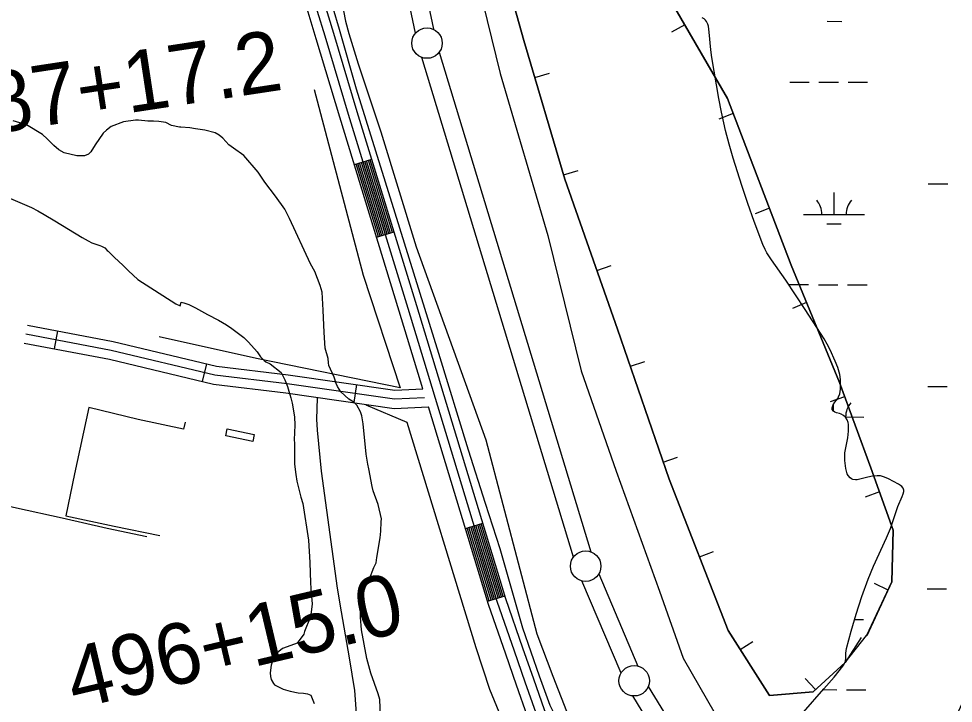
# Model space of a CAD drawing. Extents: x 3161615 to 3199515, y 867541 to 892976.
# Drawn here: x 3176709 to 3178243, y 879602 to 880727 of the extents above; entities that cross this region are included whole.
import ezdxf

# ---------------------------------------------------------------- set-up
doc = ezdxf.new("R2010")
doc.units = 0
for name, color, linetype in [('V-BLDG-OTLN', 7, 'Continuous'), ('V-BORW-LINE', 7, 'Continuous'), ('V-LEVE-TOET', 7, 'Continuous'), ('V-ROAD-CNTR', 7, 'Continuous'), ('V-SITE-VEGE', 7, 'Continuous'), ('V-SURV-IDEN', 7, 'Continuous'), ('V-SURV-LINE', 7, 'Continuous'), ('V-TOPO-SHOR', 7, 'Continuous'), ('V-UTIL-LINE', 7, 'Continuous'), ('V-WETL-SWMP', 7, 'Continuous')]:
    doc.layers.add(name, color=color, linetype=linetype)

msp = doc.modelspace()

# ---------------------------------------------------------------- linework, layer by layer
at = {"layer": 'V-BLDG-OTLN'}
msp.add_lwpolyline([(3177048.5, 880041.9), (3177050.9, 880053.1), (3177095.5, 880043.7), (3177093.1, 880032.4)], close=True, dxfattribs=at)
at = {"layer": 'V-BORW-LINE'}
for p, q in [((3177802.3, 880717.1), (3177780.7, 880704.6)), ((3177556.2, 880630.3), (3177580.2, 880637.3)), ((3177881.9, 880571.1), (3177858.6, 880562.2)), ((3177603.1, 880470.4), (3177627.1, 880477.5)), ((3177941.4, 880415.5), (3177918, 880406.6)), ((3177658.2, 880313.2), (3177681.7, 880321.5)), ((3178002.3, 880260.5), (3177979.2, 880251)), ((3177713.1, 880155.9), (3177736.7, 880164)), ((3178064.8, 880106), (3178041.3, 880097.4)), ((3177767.1, 879998.3), (3177790.7, 880006.4)), ((3178122.1, 879949.6), (3178098.6, 879941)), ((3177826.4, 879842.7), (3177849.7, 879851.7)), ((3178136.5, 879788.4), (3178113.8, 879798.9)), ((3177893.4, 879690.7), (3177914.4, 879704.1)), ((3178016.9, 879624.7), (3178000.1, 879643.1))]:
    msp.add_line(p, q, dxfattribs=at)
for points in [[(3177906.6, 882507), (3177867.3, 882300.3), (3177808.7, 882150.3), (3177775.1, 881987.1), (3177749.8, 881843.1), (3177713.2, 881626.3), (3177674.2, 881366.1), (3177662.8, 881291.6), (3177659.6, 881039.8), (3177733, 880836.9), (3177872.5, 880595.9), (3177977.1, 880322), (3178056.3, 880129.2), (3178107.7, 879988.9), (3178144.8, 879887), (3178142.7, 879801.7), (3178101.3, 879712.9)], [(3178092.2, 879710.3), (3178065.6, 879669.2), (3178013.2, 879621.3), (3177941.5, 879615.1), (3177873.5, 879721.9), (3177776.5, 879970.7), (3177692.1, 880217), (3177605.2, 880463.4), (3177538.3, 880691.4), (3177480.8, 880896.9), (3177471.8, 881055.7), (3177486.2, 881218), (3177566.2, 881651.6), (3177659.6, 882084.4), (3177695.5, 882282.8), (3177716.7, 882419.5), (3177742.6, 882484.1)], [(3177742.6, 882484.1), (3177716.7, 882419.5), (3177695.5, 882282.8), (3177659.6, 882084.4), (3177566.2, 881651.6), (3177486.2, 881218), (3177471.8, 881055.7), (3177480.8, 880896.9), (3177538.3, 880691.4), (3177605.2, 880463.4), (3177692.1, 880217), (3177776.5, 879970.7), (3177873.5, 879721.9), (3177941.5, 879615.1), (3178013.2, 879621.3), (3178065.6, 879669.2), (3178100.9, 879713.6)], [(3178100.7, 879713), (3178142.7, 879801.7), (3178144.8, 879887), (3178107.7, 879988.9), (3178056.3, 880129.2), (3177977.1, 880322), (3177872.5, 880595.9), (3177733, 880836.9), (3177659.6, 881039.8), (3177662.8, 881291.6), (3177674.2, 881366.1), (3177713.2, 881626.3), (3177749.8, 881843.1), (3177765.7, 881933.1)]]:
    msp.add_lwpolyline(points, dxfattribs=at)
at = {"layer": 'V-LEVE-TOET'}
for points in [[(3177190.1, 881032.5), (3177212.4, 880895.6), (3177219.4, 880848.2), (3177238.4, 880756.8), (3177245.2, 880722.9), (3177250.9, 880702.4), (3177266.2, 880652.8), (3177303.4, 880541.3), (3177361.3, 880352), (3177475.6, 880035.3), (3177559.5, 879716.2), (3177585.5, 879647.1), (3177608.2, 879589.3), (3177632.1, 879544), (3177652.9, 879510.5), (3177737.9, 879384.6), (3177804.7, 879295.2), (3177918.6, 879156.7), (3178101.7, 878928.5)], [(3177412.9, 881027.8), (3177449.1, 880843), (3177499.5, 880636.8), (3177577.4, 880371), (3177632.4, 880148.7), (3177689.7, 879983.7), (3177760.7, 879786.6), (3177799.6, 879676.6)], [(3177799.6, 879676.6), (3177852.3, 879585), (3177964.5, 879433.7), (3178065.3, 879314.6), (3178143.2, 879225.2), (3178214.2, 879147.3), (3178232.6, 879117.5), (3178237.1, 879094.6), (3178257.8, 878964), (3178260, 878945.7), (3178276.1, 878931.9), (3178427.3, 878842.5), (3178633.4, 878741.7), (3178715.9, 878700.5), (3178725, 878700.5), (3178768.6, 878698.2), (3179196.9, 878711.9), (3179522.2, 878730.3), (3179932.2, 878739.4), (3180383.5, 878760.1), (3180724.8, 878771.5)]]:
    msp.add_lwpolyline(points, dxfattribs=at)
at = {"layer": 'V-ROAD-CNTR'}
for p, q in [((3177259.8, 880487.4), (3177288.5, 880496.2)), ((3177296.4, 880367.9), (3177325.1, 880376.7)), ((3176772.3, 880214.2), (3176766.7, 880184.8)), ((3177017, 880160.2), (3177010.1, 880131)), ((3177263.2, 880126), (3177258.9, 880096.3)), ((3177442.2, 879889.6), (3177470.9, 879898.4)), ((3177478.6, 879770), (3177507.3, 879778.8))]:
    msp.add_line(p, q, dxfattribs=at)
for points in [[(3177372.4, 880118.9), (3177333.6, 880246.4), (3177235.9, 880565.3), (3177197.2, 880693.8), (3177172.3, 880776.4), (3177154, 880867.6), (3177149.1, 880924.8), (3177136.4, 880983.8), (3177130.2, 881055.1), (3177129, 881145.4), (3177132.9, 881223.7), (3177140, 881329.3), (3177184.4, 881632.9), (3177269.1, 882075.3), (3177338.3, 882444.5), (3177405.5, 882803.5), (3177445.5, 883028.2)], [(3177983.4, 878986.1), (3177974, 879017.1), (3177947.6, 879056.2), (3177906.3, 879105.1), (3177789.6, 879242.6), (3177686.3, 879377.3), (3177649.8, 879426.9), (3177610.6, 879487.5), (3177583.1, 879532.7), (3177558.2, 879586.1), (3177540.3, 879636.8), (3177522.5, 879688.1), (3177494.5, 879769.3), (3177348, 880250.8), (3177250.3, 880569.6), (3177211.6, 880698.1), (3177186.8, 880780.1)], [(3177997.7, 878990.5), (3177987.7, 879023.6), (3177959.5, 879065.3), (3177917.7, 879114.8), (3177801.3, 879252), (3177698.3, 879386.4), (3177662.1, 879435.4), (3177623.3, 879495.4), (3177596.3, 879539.8), (3177572.1, 879591.7), (3177554.5, 879641.8), (3177536.7, 879693.1), (3177508.7, 879774), (3177362.3, 880255.1), (3177264.6, 880574), (3177225.9, 880702.4), (3177201.4, 880783.7)], [(3177322.2, 880375.8), (3177285.6, 880495.3)], [(3177299.3, 880368.8), (3177262.7, 880488.3)], [(3177302.2, 880369.6), (3177265.5, 880489.1)], [(3177305, 880370.5), (3177268.4, 880490)], [(3177307.9, 880371.4), (3177271.3, 880490.9)], [(3177310.8, 880372.3), (3177274.1, 880491.8)], [(3177313.6, 880373.1), (3177277, 880492.7)], [(3177316.5, 880374), (3177279.9, 880493.5)], [(3177319.4, 880374.9), (3177282.8, 880494.4)], [(3176723.2, 880223.6), (3176863.8, 880196.8), (3177033.5, 880156.3), (3177151.2, 880142.1), (3177326.4, 880116.9), (3177372.4, 880118.9)], [(3177374.7, 880104), (3177325.7, 880101.8), (3177149.3, 880127.2), (3177030.8, 880141.5), (3176860.6, 880182.1), (3176720.4, 880208.9)], [(3176717.6, 880194.2), (3176857.5, 880167.5), (3177028.2, 880126.7), (3177147.3, 880112.3), (3177324.9, 880086.8), (3177381.4, 880089.3)], [(3177955.1, 878644.3), (3177980.3, 878696.2), (3177990.9, 878727.9), (3178000, 878775.1), (3178003.8, 878817), (3177999.2, 878855.2), (3177993.5, 878899.8), (3177979.8, 878946.2), (3177969, 878981.8), (3177960.3, 879010.6), (3177935.6, 879047.2), (3177894.8, 879095.4), (3177777.9, 879233.1), (3177674.4, 879368.3), (3177637.4, 879418.3), (3177597.9, 879479.5), (3177569.8, 879525.6), (3177544.3, 879580.4), (3177526.2, 879631.9), (3177508.4, 879683.2), (3177480.2, 879764.7), (3177381.4, 880089.3)], [(3177504.4, 879777.9), (3177468, 879897.5)], [(3177481.4, 879770.9), (3177445.1, 879890.5)], [(3177484.3, 879771.8), (3177447.9, 879891.4)], [(3177487.2, 879772.7), (3177450.8, 879892.2)], [(3177490, 879773.5), (3177453.7, 879893.1)], [(3177492.9, 879774.4), (3177456.5, 879894)], [(3177495.8, 879775.3), (3177459.4, 879894.9)], [(3177498.7, 879776.1), (3177462.3, 879895.7)], [(3177501.5, 879777), (3177465.1, 879896.6)]]:
    msp.add_lwpolyline(points, dxfattribs=at)
at = {"layer": 'V-SITE-VEGE'}
for p, q in [((3176721.3, 880552.5), (3176699.5, 880559.3)), ((3176880.4, 880557.4), (3176860.2, 880550.1)), ((3176900.6, 880560.4), (3176880.4, 880557.4)), ((3176905.3, 880560.4), (3176900.6, 880560.4)), ((3176920.8, 880558.9), (3176905.3, 880560.4)), ((3176929.8, 880558.9), (3176920.8, 880558.9)), ((3176938.9, 880558.2), (3176929.8, 880558.9)), ((3176950, 880556.4), (3176938.9, 880558.2)), ((3176747.5, 880536.5), (3176721.3, 880552.5)), ((3176852.8, 880544.1), (3176847, 880538.8)), ((3176860.2, 880550.1), (3176852.8, 880544.1)), ((3176959.7, 880551.7), (3176950, 880556.4)), ((3176972.8, 880548.9), (3176959.7, 880551.7)), ((3176974.8, 880548.9), (3176972.8, 880548.9)), ((3176989.6, 880547.9), (3176974.8, 880548.9)), ((3176999, 880546.1), (3176989.6, 880547.9)), ((3177014.2, 880543.7), (3176999, 880546.1)), ((3177031.3, 880539.6), (3177014.2, 880543.7)), ((3176755.2, 880529.8), (3176747.5, 880536.5)), ((3176766.2, 880518.6), (3176755.2, 880529.8)), ((3176847, 880538.8), (3176834.1, 880519.7)), ((3177038, 880535.5), (3177031.3, 880539.6)), ((3177043.7, 880530.8), (3177038, 880535.5)), ((3177053.7, 880519.6), (3177043.7, 880530.8)), ((3176774.3, 880511.5), (3176766.2, 880518.6)), ((3176783, 880506.8), (3176774.3, 880511.5)), ((3176834.1, 880519.7), (3176827, 880508.3)), ((3177061.1, 880514.2), (3177053.7, 880519.6)), ((3177078.2, 880502.4), (3177061.1, 880514.2)), ((3176804.1, 880501.6), (3176783, 880506.8)), ((3176816.6, 880501.9), (3176804.1, 880501.6)), ((3176823, 880504.2), (3176816.6, 880501.9)), ((3176827, 880508.3), (3176823, 880504.2)), ((3177101.6, 880474.7), (3177078.2, 880502.4)), ((3177113, 880458.5), (3177101.6, 880474.7)), ((3177130.3, 880435.6), (3177113, 880458.5)), ((3176687.5, 880434.9), (3176729.8, 880416.9)), ((3177145.4, 880414), (3177130.3, 880435.6)), ((3176729.8, 880416.9), (3176739.8, 880411.5)), ((3176739.8, 880411.5), (3176750.2, 880405.4)), ((3176750.2, 880405.4), (3176768, 880394.9)), ((3177153.4, 880398.8), (3177145.4, 880414)), ((3176768, 880394.9), (3176812.6, 880367.8)), ((3177187.7, 880324), (3177153.4, 880398.8)), ((3176812.6, 880367.8), (3176822.7, 880362.3)), ((3176822.7, 880362.3), (3176828.4, 880359)), ((3176828.4, 880359), (3176833.4, 880356.9)), ((3176833.4, 880356.9), (3176841.8, 880354.2)), ((3176841.8, 880354.2), (3176844.5, 880353.2)), ((3176844.5, 880353.2), (3176849.8, 880350.5)), ((3176849.8, 880350.5), (3176853.9, 880346.4)), ((3176853.9, 880346.4), (3176855.5, 880345)), ((3176855.5, 880345), (3176865.9, 880334.6)), ((3176865.9, 880334.6), (3176879.3, 880322.1)), ((3176879.3, 880322.1), (3176888.7, 880312.9)), ((3176888.7, 880312.9), (3176904.4, 880298.4)), ((3177194.7, 880311.5), (3177187.7, 880324)), ((3177203.6, 880288.6), (3177194.7, 880311.5)), ((3176904.4, 880298.4), (3176966.4, 880258.8)), ((3177206.9, 880277.5), (3177203.6, 880288.6)), ((3177208.5, 880248.2), (3177206.9, 880277.5)), ((3176966.4, 880258.8), (3176973.8, 880255)), ((3176973.8, 880255), (3176975.5, 880261.4)), ((3176975.5, 880261.4), (3176979.9, 880260.4)), ((3176979.9, 880260.4), (3176987.9, 880257.7)), ((3176987.9, 880257.7), (3176999, 880252.2)), ((3176999, 880252.2), (3177018.8, 880241.1)), ((3177018.8, 880241.1), (3177036.6, 880231.6)), ((3177210, 880211.2), (3177208.5, 880248.2)), ((3177036.6, 880231.6), (3177050, 880224.1)), ((3177050, 880224.1), (3177058.4, 880218.3)), ((3177058.4, 880218.3), (3177078.5, 880203.1)), ((3177211.9, 880185.7), (3177210, 880211.2)), ((3177078.5, 880203.1), (3177086.2, 880195.7)), ((3177086.2, 880195.7), (3177099.9, 880179.5)), ((3177099.9, 880179.5), (3177105.9, 880171.4)), ((3177216.5, 880168.8), (3177211.9, 880185.7)), ((3177105.9, 880171.4), (3177111.6, 880165.3)), ((3177111.6, 880165.3), (3177114.6, 880163.3)), ((3177114.6, 880163.3), (3177121.3, 880160.2)), ((3177121.3, 880160.2), (3177139.7, 880146)), ((3177217.2, 880161.4), (3177216.5, 880168.8)), ((3177217.8, 880157.4), (3177217.2, 880161.4)), ((3177139.7, 880146), (3177145.7, 880133.5)), ((3177226.5, 880138.2), (3177217.8, 880157.4)), ((3177145.7, 880133.5), (3177150.1, 880122.7)), ((3177230.1, 880127.8), (3177226.5, 880138.2)), ((3177232.1, 880122.7), (3177230.1, 880127.8)), ((3177150.1, 880122.7), (3177152.4, 880115.3)), ((3177152.4, 880115.3), (3177155.7, 880104.2)), ((3177237.4, 880113.9), (3177232.1, 880122.7)), ((3177250.5, 880102.1), (3177237.4, 880113.9)), ((3177155.7, 880104.2), (3177157.7, 880095.5)), ((3177258.9, 880097), (3177250.5, 880102.1)), ((3177263.9, 880091.9), (3177258.9, 880097)), ((3177157.7, 880095.5), (3177161.6, 880072.9)), ((3177269.9, 880081.2), (3177263.9, 880091.9)), ((3177271.9, 880074.4), (3177269.9, 880081.2)), ((3177161.6, 880072.9), (3177162.2, 880059.5)), ((3177274.5, 880061.6), (3177271.9, 880074.4)), ((3177162.2, 880059.5), (3177161.1, 880034.9)), ((3177279.3, 880011.5), (3177274.5, 880061.6)), ((3177161.1, 880034.9), (3177161.4, 880029.5)), ((3177161.4, 880029.5), (3177161.6, 879995.2)), ((3177282, 879995.4), (3177279.3, 880011.5)), ((3177161.6, 879995.2), (3177163.8, 879978.1)), ((3177283.6, 879987.6), (3177282, 879995.4)), ((3177163.8, 879978.1), (3177165.1, 879967)), ((3177289.2, 879958.3), (3177283.6, 879987.6)), ((3177165.1, 879967), (3177171.7, 879941.1)), ((3177290.8, 879951.3), (3177289.2, 879958.3)), ((3177298.8, 879928.7), (3177290.8, 879951.3)), ((3177171.7, 879941.1), (3177175.1, 879930.6)), ((3177175.1, 879930.6), (3177184.2, 879870.4)), ((3177304.1, 879905.5), (3177298.8, 879928.7)), ((3177303, 879885.3), (3177304, 879900.4)), ((3177304, 879900.4), (3177304.1, 879905.5)), ((3177301.9, 879873.9), (3177303, 879885.3)), ((3177184.2, 879870.4), (3177186.4, 879833.4)), ((3177296.7, 879842), (3177301.9, 879873.9)), ((3177295.7, 879833.2), (3177296.7, 879842)), ((3177186.4, 879833.4), (3177187.6, 879800.4)), ((3177284.8, 879807), (3177291.6, 879825.2)), ((3177291.6, 879825.2), (3177295.7, 879833.2)), ((3177278.3, 879794.3), (3177284.8, 879807)), ((3177187.6, 879800.4), (3177188.2, 879791.4)), ((3177188.2, 879791.4), (3177188.2, 879789)), ((3177272.2, 879776.2), (3177278.3, 879794.3)), ((3177188.2, 879789), (3177190.4, 879765.8)), ((3177269.8, 879764.1), (3177272.2, 879776.2)), ((3177190.4, 879765.8), (3177189, 879752)), ((3177270, 879743.9), (3177269.8, 879764.1)), ((3177187.3, 879743.3), (3177177.8, 879720.1)), ((3177189, 879752), (3177187.3, 879743.3)), ((3177271.6, 879723), (3177270, 879743.9)), ((3177176.7, 879715.7), (3177165.6, 879701.3)), ((3177177.8, 879720.1), (3177176.7, 879715.7)), ((3177280.1, 879675.9), (3177271.6, 879723)), ((3177165.6, 879701.3), (3177149.4, 879695)), ((3177132.9, 879685), (3177128.8, 879680)), ((3177141.7, 879692.4), (3177132.9, 879685)), ((3177149.4, 879695), (3177141.7, 879692.4)), ((3177127.1, 879677.3), (3177123, 879665.2)), ((3177128.8, 879680), (3177127.1, 879677.3)), ((3177287.1, 879652), (3177280.1, 879675.9)), ((3177123, 879665.2), (3177121.6, 879652.5)), ((3177121.6, 879652.5), (3177121.9, 879646.4)), ((3177298.7, 879618), (3177287.1, 879652)), ((3177121.9, 879646.4), (3177123.3, 879641.3)), ((3177123.3, 879641.3), (3177126.9, 879634.6)), ((3177126.9, 879634.6), (3177128.9, 879632.9)), ((3177128.9, 879632.9), (3177142.7, 879625.5)), ((3177142.7, 879625.5), (3177154.4, 879622)), ((3177154.4, 879622), (3177167.5, 879619.6)), ((3177167.5, 879619.6), (3177176, 879618.9)), ((3177176, 879618.9), (3177182.7, 879617.9)), ((3177182.7, 879617.9), (3177188.4, 879615.5)), ((3177188.4, 879615.5), (3177194, 879601.7)), ((3177301.7, 879608.6), (3177298.7, 879618)), ((3177302.9, 879581), (3177301.7, 879608.6))]:
    msp.add_line(p, q, dxfattribs=at)
for points in [[(3178066.1, 880072.5), (3178063, 880075.3), (3178059.5, 880077.4), (3178056.4, 880078.6), (3178051.4, 880079.7), (3178048.9, 880080.6), (3178046.6, 880082.4), (3178044.6, 880085.1), (3178044.2, 880086.5), (3178044.3, 880087.9), (3178046.2, 880092.5), (3178048.8, 880097.1), (3178053.7, 880103.2), (3178055, 880105.6), (3178056.8, 880110.6), (3178058.1, 880118.3), (3178058.3, 880126), (3178058.1, 880134.4), (3178056.8, 880142.7), (3178053.5, 880153.8), (3178049.3, 880164.5), (3178040.9, 880183.1), (3178036.4, 880192.2), (3178031.3, 880201), (3178000.2, 880249.4), (3177968.4, 880297.3), (3177944.8, 880330.8), (3177937.3, 880342.3), (3177934.3, 880347.6), (3177930.7, 880355.9), (3177916.5, 880393.7), (3177906.1, 880423.3), (3177896.1, 880453.1), (3177881.9, 880498), (3177875.4, 880520.6), (3177869.2, 880543.5), (3177862.5, 880573.2), (3177858.2, 880595.7), (3177847.1, 880663.3), (3177845.4, 880676), (3177842.7, 880704.9), (3177841.3, 880714.5), (3177840.4, 880717.9), (3177837.9, 880722.6), (3177836.2, 880724.7), (3177834.2, 880726.5), (3177830.9, 880728.6)], [(3177997.3, 879588), (3178030.9, 879626.1), (3178047.7, 879645.4), (3178055.8, 879655.4), (3178063.6, 879665.7), (3178065.3, 879668.7), (3178066.2, 879671.4), (3178066.9, 879676.5), (3178067, 879684.5), (3178067.2, 879688.5), (3178067.9, 879692.3), (3178075.6, 879720.7), (3178083.9, 879749), (3178093.3, 879777.9), (3178103.5, 879806.4), (3178112.2, 879827.4), (3178133.5, 879873.9), (3178140, 879889.7), (3178152.3, 879925.4), (3178159.5, 879942.2), (3178161, 879946.4), (3178162, 879950.5), (3178162, 879952.5), (3178160.8, 879955.5), (3178158.6, 879958.3), (3178156.5, 879960.2), (3178153.2, 879962.3), (3178136.9, 879971.1), (3178130.4, 879974), (3178123.6, 879975.8), (3178118.6, 879976.1), (3178110.8, 879975.2), (3178103.2, 879973.8), (3178085.6, 879969.6), (3178082.6, 879969.4), (3178078.3, 879970.2), (3178076.1, 879971.3), (3178073.9, 879972.9), (3178070.8, 879976.4), (3178069.3, 879979.1), (3178067.9, 879983.5), (3178067.1, 879988.1), (3178065.3, 880001), (3178065, 880007.4), (3178065.4, 880013.8), (3178070.3, 880038.6), (3178071.4, 880049.3), (3178071.4, 880060.1), (3178070.9, 880063.4), (3178069.1, 880068.1), (3178066.1, 880072.5)]]:
    msp.add_lwpolyline(points, dxfattribs=at)
at = {"layer": 'V-SURV-LINE'}
for points in [[(3177360.3, 880703.4), (3177312.6, 880930)], [(3177341.9, 880936.2), (3177389.6, 880709.6)], [(3177399.2, 880672.1), (3177648.2, 879851.1)], [(3177619.5, 879842.4), (3177370.5, 880663.4)], [(3177661.2, 879815.1), (3177725.3, 879663.5)], [(3177697.7, 879651.8), (3177633.6, 879803.4)], [(3177742.5, 879630), (3177819.2, 879504.2)], [(3177793.6, 879488.5), (3177716.9, 879614.4)]]:
    msp.add_lwpolyline(points, dxfattribs=at)
for centre in [(3177379.1, 880686.9), (3177639.6, 879827.6), (3177719.3, 879639.3)]:
    msp.add_circle(centre, 25, dxfattribs=at)
at = {"layer": 'V-TOPO-SHOR'}
for points in [[(3177447.3, 880018.1), (3177398.5, 880177), (3177326.7, 880407.6), (3177263.5, 880611), (3177235.4, 880709), (3177214.3, 880780.1), (3177198.2, 880854.5), (3177186.5, 880951.7), (3177177.1, 881048.6), (3177172.9, 881152.5), (3177175.7, 881243.1), (3177182.8, 881331.7), (3177196.1, 881421.5), (3177214.6, 881525.5), (3177241.5, 881675.7)], [(3177193.9, 880610.9), (3177274.1, 880305.9), (3177335.2, 880120.7), (3177099.3, 880168.9), (3176939.1, 880204.6)], [(3177264.3, 879570.2), (3177260.5, 879623.5), (3177252, 879676.9), (3177238.5, 879752.4), (3177232.3, 879791.3), (3177206, 879983.4), (3177199.5, 880050.9), (3177198.1, 880069.2), (3177199.4, 880103.6)], [(3177278.8, 880092.7), (3177345.7, 880064.3), (3177459.1, 879694.1), (3177481.8, 879625.3), (3177515.1, 879544.2), (3177578.2, 879434.8), (3177761.5, 879208)], [(3178047.7, 878781.1), (3178049.1, 878827.5), (3178047.6, 878865.8), (3178044.1, 878888.2), (3178035, 878925.6), (3178025, 878958.4), (3178009.9, 879006.1), (3178000.7, 879025.5), (3177981.3, 879054.2), (3177957, 879087.5), (3177907.2, 879149.8), (3177773.5, 879316.2), (3177692.3, 879417.4), (3177645.1, 879484.6), (3177622.6, 879521.3), (3177602.7, 879555.7), (3177581.5, 879598.9), (3177563.8, 879646.7), (3177536.4, 879726), (3177499, 879856.3), (3177474.9, 879930.7), (3177447.3, 880018.1)]]:
    msp.add_lwpolyline(points, dxfattribs=at)
at = {"layer": 'V-UTIL-LINE'}
for points in [[(3176982, 880064.3), (3176979.4, 880052.8), (3176904.9, 880068.7), (3176823.6, 880088.3), (3176800.4, 879979.1), (3176786, 879910.3), (3176865.3, 879893.2), (3176940.4, 879878)], [(3176918.7, 879875.9), (3176853.8, 879889.5), (3176779.7, 879906.3), (3176705.1, 879923.1), (3176655.9, 879934)]]:
    msp.add_lwpolyline(points, dxfattribs=at)
at = {"layer": 'V-WETL-SWMP'}
for p, q in [((3178036.4, 880722.7), (3178060.4, 880722.6)), ((3177974.7, 880622.8), (3178006.7, 880622.7)), ((3178022.7, 880622.7), (3178054.7, 880622.6)), ((3178070.7, 880622.6), (3178102.7, 880622.5)), ((3178202.2, 880455.7), (3178234.2, 880455.6)), ((3178047.5, 880405.4), (3178047.6, 880441.4)), ((3177997.5, 880405.5), (3178097.5, 880405.3)), ((3178035.5, 880390), (3178059.5, 880389.9)), ((3177973.8, 880290.2), (3178005.8, 880290.1)), ((3178021.8, 880290), (3178053.8, 880289.9)), ((3178069.8, 880289.9), (3178101.8, 880289.8)), ((3178201.3, 880123), (3178233.3, 880122.9)), ((3178046.6, 880082.4), (3178046.6, 880093.3)), ((3178065.9, 880072.7), (3178096.6, 880072.6)), ((3178200.4, 879790.4), (3178232.4, 879790.3)), ((3178081.3, 879739.9), (3178095.7, 879739.9)), ((3178029.6, 879624.7), (3178051.9, 879624.6)), ((3178067.9, 879624.5), (3178099.9, 879624.5))]:
    msp.add_line(p, q, dxfattribs=at)
for points in [[(3178067, 879684.5), (3178067.2, 879688.5), (3178067.9, 879692.3), (3178075.6, 879720.7), (3178083.9, 879749), (3178093.3, 879777.8), (3178103.5, 879806.4), (3178112.2, 879827.4), (3178133.5, 879873.9), (3178140, 879889.7), (3178152.3, 879925.4), (3178159.5, 879942.2), (3178161, 879946.4), (3178162, 879950.5), (3178162, 879952.5), (3178160.8, 879955.5), (3178158.6, 879958.3), (3178156.5, 879960.2), (3178153.2, 879962.2), (3178136.9, 879971.1), (3178130.4, 879974), (3178123.6, 879975.8), (3178118.6, 879976.1), (3178110.8, 879975.2), (3178103.2, 879973.8), (3178085.6, 879969.6), (3178082.6, 879969.4), (3178078.3, 879970.2), (3178076.1, 879971.3), (3178073.9, 879972.9), (3178070.8, 879976.4), (3178069.3, 879979.1), (3178067.9, 879983.5), (3178067.1, 879988.1), (3178065.3, 880001), (3178065, 880007.4), (3178065.4, 880013.8), (3178070.3, 880038.6), (3178071.4, 880049.3), (3178071.4, 880060.1), (3178070.9, 880063.4), (3178069.1, 880068.1), (3178066.1, 880072.5), (3178063, 880075.3), (3178059.5, 880077.4), (3178056.4, 880078.6), (3178051.4, 880079.7), (3178048.9, 880080.6), (3178046.6, 880082.4), (3178044.6, 880085.1), (3178044.2, 880086.5), (3178044.3, 880087.9), (3178046.2, 880092.5), (3178048.8, 880097.1), (3178053.7, 880103.2), (3178055, 880105.6), (3178056.8, 880110.6), (3178058.1, 880118.3), (3178058.3, 880126), (3178058.1, 880134.4), (3178056.8, 880142.7), (3178053.5, 880153.8), (3178049.3, 880164.5), (3178040.9, 880183.1), (3178036.3, 880192.2), (3178031.3, 880201), (3178000.2, 880249.4), (3177968.4, 880297.3), (3177944.8, 880330.8), (3177937.3, 880342.3), (3177934.3, 880347.6), (3177930.7, 880355.9), (3177916.5, 880393.7), (3177906.1, 880423.3), (3177896.1, 880453.1), (3177881.9, 880498), (3177875.4, 880520.6), (3177869.2, 880543.5), (3177862.5, 880573.2), (3177858.2, 880595.7), (3177847.1, 880663.3), (3177845.4, 880676), (3177842.7, 880704.9), (3177841.3, 880714.5), (3177840.4, 880717.9), (3177837.9, 880722.6), (3177836.2, 880724.7), (3177834.2, 880726.5), (3177830.9, 880728.6)], [(3178302.7, 879701.8), (3178230.4, 879542.5), (3178143.5, 879441.2), (3178027.8, 879441.2), (3177955.9, 879552.2), (3177958.4, 879551.8), (3177961.8, 879552.1), (3177964.4, 879552.7), (3177968.2, 879554.5), (3177971.7, 879557.1), (3177978.9, 879564.8), (3177997.3, 879588), (3178030.9, 879626.1), (3178047.7, 879645.4), (3178055.8, 879655.4), (3178063.6, 879665.7), (3178065.3, 879668.7), (3178066.2, 879671.4), (3178066.9, 879676.5), (3178067, 879684.5)]]:
    msp.add_lwpolyline(points, dxfattribs=at)
for centre, start, end in [((3177992.3, 880406), 359.0699, 40.6135), ((3178102.7, 880405.7), 139.0699, 180.6135), ((3178101.8, 880073), 139.0699, 180.6135)]:
    msp.add_arc(centre, 35.2, start, end, dxfattribs=at)

# ---------------------------------------------------------------- texts
at = {"layer": 'V-SURV-IDEN'}
for s, rotation, p in [('487+17.2', 8.643, (3176590.3, 880526.4)), ('496+15.0', 13.3151, (3176800.5, 879592.2))]:
    msp.add_text(s, height=100, rotation=rotation, dxfattribs=at).set_placement(p)

doc.saveas('drawing.dxf')
